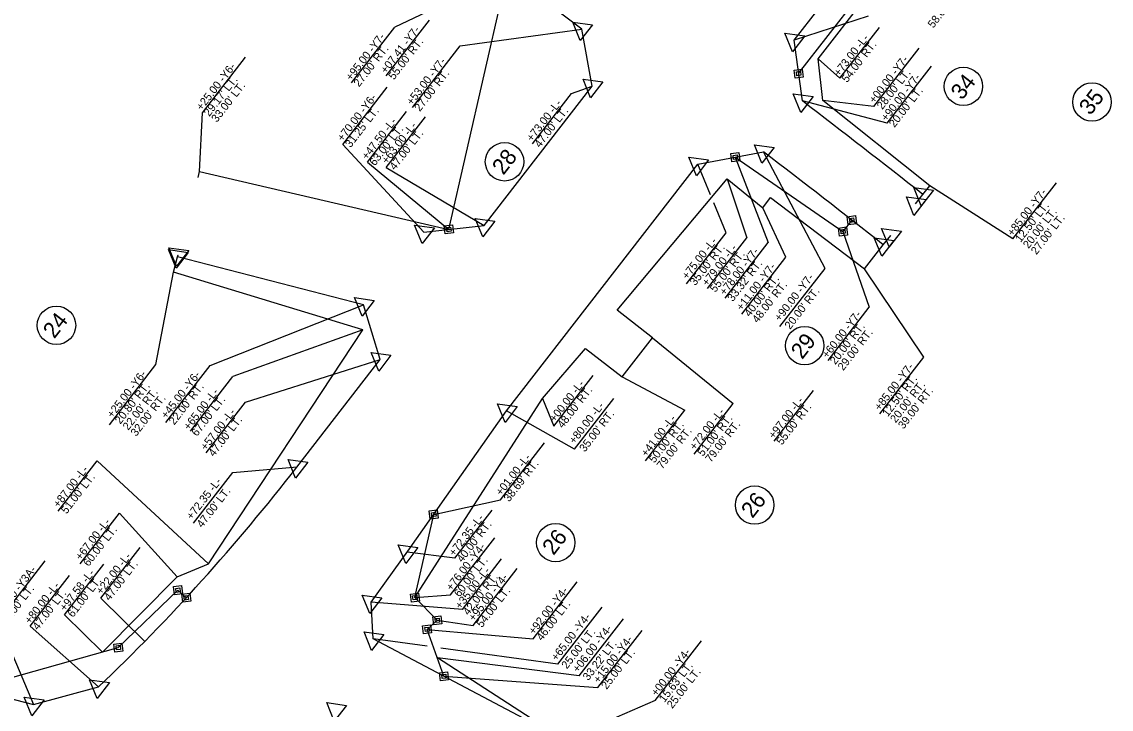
# Model space of a CAD drawing. Extents: x 2010883 to 2014849, y 442000 to 447413.
# Drawn here: x 2014042 to 2014722, y 445299 to 445728 of the extents above; entities that cross this region are included whole.
import ezdxf

# ---------------------------------------------------------------- set-up
doc = ezdxf.new("R2010")
doc.units = 0
for name, color, linetype in [('Prop Easement Construction', 7, 'Continuous'), ('Prop Easement Construction Station Offsets', 7, 'Continuous'), ('Prop Easement Permanent Drainage Utility', 7, 'Continuous'), ('Prop Easement Permanent Drainage Utility Station Offsets', 7, 'Continuous'), ('Prop Easement Permanent Utility', 7, 'Continuous'), ('Prop Easement Permanent Utility Station Offsets', 7, 'Continuous'), ('Prop Parcel Number CELL', 7, 'Continuous'), ('Prop Parcel Number Text', 7, 'Continuous'), ('Prop ROW Marker CELL', 7, 'Continuous'), ('Prop ROW Permanent Easement CELL', 7, 'Continuous'), ('Prop ROW RW Lines', 7, 'Continuous'), ('Prop ROW Station Offsets', 7, 'Continuous')]:
    doc.layers.add(name, color=color, linetype=linetype)

msp = doc.modelspace()

# ---------------------------------------------------------------- linework, layer by layer
at = {"layer": 'Prop Easement Construction'}
for p, q in [((2014539.38, 445704.73), (2014617.83, 445805.87)), ((2014542.4, 445678.69), (2014539.38, 445704.73)), ((2014609.15, 445625.51), (2014542.4, 445678.69)), ((2014152.11, 445630.72), (2014153.06, 445634.43)), ((2014153.06, 445634.43), (2014308.73, 445598.23)), ((2014413.83, 445547.73), (2014482.57, 445629.84)), ((2014482.57, 445629.84), (2014504.77, 445611.75)), ((2014604.82, 445620.01), (2014609.15, 445625.51)), ((2014504.77, 445611.75), (2014509.66, 445618.09)), ((2014509.66, 445618.09), (2014568.31, 445573.66)), ((2014568.31, 445573.66), (2014580.07, 445588.59)), ((2014136.82, 445571.49), (2014139.32, 445581.17)), ((2014255.01, 445535.5), (2014136.82, 445571.49)), ((2014435.96, 445530.58), (2014413.83, 445547.73)), ((2014158.53, 445389.38), (2014255.01, 445535.5)), ((2014416.96, 445506.08), (2014435.96, 445530.58)), ((2014367.34, 445492.68), (2014394.04, 445523.85)), ((2014394.04, 445523.85), (2014416.96, 445506.08)), ((2014287.55, 445368.24), (2014367.34, 445492.68)), ((2014139.04, 445381.17), (2014158.53, 445389.38)), ((2014092.37, 445334.23), (2014139.04, 445381.17)), ((2014380.88, 445279.41), (2014301.58, 445330.55))]:
    msp.add_line(p, q, dxfattribs=at)
at = {"layer": 'Prop Easement Construction Station Offsets'}
for p, q in [((2014269.69, 445694.09), (2014296.66, 445728.85)), ((2014553.01, 445692.61), (2014577.65, 445724.38)), ((2014574.22, 445675.03), (2014602.41, 445711.38)), ((2014154.86, 445671.14), (2014181.82, 445705.91)), ((2014553.01, 445692.61), (2014539.38, 445704.73)), ((2014574.22, 445675.03), (2014542.4, 445678.69)), ((2014153.06, 445634.43), (2014154.86, 445671.14)), ((2014482.57, 445629.84), (2014494.8, 445593.01)), ((2014519.22, 445580.94), (2014504.77, 445611.75)), ((2014470.29, 445561.4), (2014494.8, 445593.01)), ((2014491.64, 445545.38), (2014519.22, 445580.94)), ((2014255.01, 445535.5), (2014173.91, 445506.4)), ((2014435.96, 445530.58), (2014486.38, 445489.46)), ((2014147.4, 445472.22), (2014173.91, 445506.4)), ((2014374.34, 445475.39), (2014398.85, 445507)), ((2014416.96, 445506.08), (2014456.06, 445485.3)), ((2014367.34, 445492.68), (2014374.34, 445475.39)), ((2014431.55, 445453.69), (2014456.06, 445485.3)), ((2014461.87, 445457.85), (2014486.38, 445489.46)), ((2014064.63, 445422.14), (2014089.14, 445453.75)), ((2014158.53, 445389.38), (2014089.14, 445453.75)), ((2014078.46, 445389.31), (2014102.97, 445420.92)), ((2014139.04, 445381.17), (2014102.97, 445420.92)), ((2014068.66, 445357.45), (2014093.17, 445389.06)), ((2014092.37, 445334.23), (2014068.66, 445357.45))]:
    msp.add_line(p, q, dxfattribs=at)
at = {"layer": 'Prop Easement Permanent Drainage Utility'}
msp.add_line((2014308.73, 445598.23), (2014345.35, 445758.1), dxfattribs=at)
at = {"layer": 'Prop Easement Permanent Drainage Utility Station Offsets'}
for p, q in [((2014345.35, 445758.1), (2014274.92, 445724.48)), ((2014247.95, 445689.71), (2014274.92, 445724.48)), ((2014257.87, 445640.26), (2014282.39, 445671.87)), ((2014257.87, 445640.26), (2014308.73, 445598.23))]:
    msp.add_line(p, q, dxfattribs=at)
at = {"layer": 'Prop Easement Permanent Utility'}
for p, q in [((2014527.22, 445695.57), (2014614.67, 445808.33)), ((2014555.48, 445658.51), (2014555.48, 445658.51)), ((2014487.67, 445643.35), (2014554.91, 445596.89)), ((2014560.46, 445603.98), (2014554.91, 445596.89)), ((2014287.55, 445368.24), (2014299.31, 445420.15)), ((2014102.28, 445337), (2014139.57, 445372.88)), ((2014144.72, 445368.14), (2014139.57, 445372.88)), ((2014301.55, 445354.06), (2014287.55, 445368.24)), ((2014295.17, 445348.39), (2014301.55, 445354.06)), ((2014305.71, 445319.08), (2014295.17, 445348.39)), ((2014020.47, 445314.08), (2014102.28, 445337))]:
    msp.add_line(p, q, dxfattribs=at)
at = {"layer": 'Prop Easement Permanent Utility Station Offsets'}
for p, q in [((2014487.67, 445643.35), (2014508.28, 445589.95)), ((2014554.91, 445596.89), (2014571.27, 445549.56)), ((2014481.31, 445555.18), (2014508.28, 445589.95)), ((2014545.57, 445516.43), (2014571.27, 445549.56)), ((2014512, 445465.91), (2014536.51, 445497.52)), ((2014340.94, 445429.35), (2014368.51, 445464.91)), ((2014299.31, 445420.15), (2014340.94, 445429.35)), ((2014309.87, 445369.91), (2014337.45, 445405.47)), ((2014091.44, 445367.84), (2014115.95, 445399.45)), ((2014323.91, 445350.84), (2014351.48, 445386.4)), ((2014361.4, 445342.54), (2014388.98, 445378.1)), ((2014287.55, 445368.24), (2014309.87, 445369.91)), ((2014118.81, 445340.9), (2014091.44, 445367.84)), ((2014295.17, 445348.39), (2014361.4, 445342.54)), ((2014301.55, 445354.06), (2014323.91, 445350.84)), ((2014401.83, 445312.18), (2014429.41, 445347.74)), ((2014305.71, 445319.08), (2014401.83, 445312.18))]:
    msp.add_line(p, q, dxfattribs=at)
at = {"layer": 'Prop Parcel Number CELL'}
for p, q in [((2014630.14, 445687.57), (2014630.14, 445687.57)), ((2014710.45, 445677.79), (2014710.45, 445677.79)), ((2014343.53, 445640.46), (2014343.53, 445640.46)), ((2014063.67, 445538.3), (2014063.67, 445538.3)), ((2014531.02, 445525.59), (2014531.02, 445525.59)), ((2014499.75, 445426.02), (2014499.75, 445426.02)), ((2014375.49, 445402.58), (2014375.49, 445402.58))]:
    msp.add_line(p, q, dxfattribs=at)
for centre in [(2014630.14, 445687.57), (2014710.45, 445677.79), (2014343.53, 445640.46), (2014063.67, 445538.3), (2014531.02, 445525.59), (2014499.75, 445426.02), (2014375.49, 445402.58)]:
    msp.add_circle(centre, 12, dxfattribs=at)
at = {"layer": 'Prop ROW Marker CELL'}
for p, q in [((2014391.79, 445723.35), (2014391.79, 445723.35)), ((2014524.37, 445716.37), (2014524.37, 445716.37)), ((2014527.22, 445695.57), (2014527.22, 445695.57)), ((2014398.29, 445687.6), (2014398.29, 445687.6)), ((2014529.57, 445678.45), (2014529.57, 445678.45)), ((2014487.67, 445643.35), (2014487.67, 445643.35)), ((2014505.25, 445646.68), (2014505.25, 445646.68)), ((2014464.31, 445638.93), (2014464.31, 445638.93)), ((2014600.18, 445614.12), (2014600.18, 445614.12)), ((2014604.82, 445620.01), (2014604.82, 445620.01)), ((2014330.88, 445600.68), (2014330.88, 445600.68)), ((2014560.46, 445603.98), (2014560.46, 445603.98)), ((2014293.03, 445596.5), (2014293.03, 445596.5)), ((2014308.73, 445598.23), (2014308.73, 445598.23)), ((2014554.91, 445596.89), (2014554.91, 445596.89)), ((2014584.71, 445594.48), (2014584.71, 445594.48)), ((2014580.07, 445588.59), (2014580.07, 445588.59)), ((2014139.32, 445581.17), (2014139.32, 445581.17)), ((2014139.62, 445582.33), (2014139.62, 445582.33)), ((2014255.51, 445551.19), (2014255.51, 445551.19)), ((2014265.92, 445516.92), (2014265.92, 445516.92)), ((2014344.81, 445484.84), (2014344.81, 445484.84)), ((2014214.04, 445450.02), (2014214.04, 445450.02)), ((2014299.31, 445420.15), (2014299.31, 445420.15)), ((2014282.78, 445396.71), (2014282.78, 445396.71)), ((2014139.57, 445372.88), (2014139.57, 445372.88)), ((2014144.72, 445368.14), (2014144.72, 445368.14)), ((2014260.31, 445365.36), (2014260.31, 445365.36)), ((2014287.55, 445368.24), (2014287.55, 445368.24)), ((2014295.17, 445348.39), (2014295.17, 445348.39)), ((2014301.55, 445354.06), (2014301.55, 445354.06)), ((2014261.49, 445342.42), (2014261.49, 445342.42)), ((2014102.28, 445337), (2014102.28, 445337)), ((2014305.71, 445319.08), (2014305.71, 445319.08)), ((2014090.02, 445312.45), (2014090.02, 445312.45)), ((2014049.27, 445301.55), (2014049.27, 445301.55))]:
    msp.add_line(p, q, dxfattribs=at)
for points in [[(2014390.8, 445716.21), (2014386.1, 445727.76), (2014398.46, 445726.09)], [(2014523.38, 445709.23), (2014518.68, 445720.78), (2014531.04, 445719.1)], [(2014397.3, 445680.46), (2014392.6, 445692.02), (2014404.96, 445690.34)], [(2014528.58, 445671.3), (2014523.88, 445682.86), (2014536.24, 445681.18)], [(2014504.27, 445639.54), (2014499.56, 445651.09), (2014511.93, 445649.42)], [(2014463.33, 445631.79), (2014458.62, 445643.34), (2014470.99, 445641.66)], [(2014603.83, 445612.87), (2014599.13, 445624.42), (2014611.49, 445622.74)], [(2014599.19, 445606.97), (2014594.49, 445618.53), (2014606.85, 445616.85)], [(2014292.04, 445589.35), (2014287.34, 445600.91), (2014299.7, 445599.23)], [(2014329.89, 445593.54), (2014325.19, 445605.09), (2014337.55, 445603.41)], [(2014583.72, 445587.34), (2014579.02, 445598.89), (2014591.38, 445597.21)], [(2014138.63, 445575.19), (2014133.93, 445586.74), (2014146.29, 445585.06)], [(2014579.08, 445581.44), (2014574.38, 445593), (2014586.74, 445591.32)], [(2014138.34, 445574.03), (2014133.63, 445585.58), (2014146, 445583.9)], [(2014254.53, 445544.04), (2014249.83, 445555.6), (2014262.19, 445553.92)], [(2014264.93, 445509.77), (2014260.23, 445521.33), (2014272.59, 445519.65)], [(2014343.82, 445477.7), (2014339.12, 445489.25), (2014351.48, 445487.57)], [(2014213.05, 445442.88), (2014208.35, 445454.44), (2014220.71, 445452.76)], [(2014281.8, 445389.56), (2014277.1, 445401.12), (2014289.46, 445399.44)], [(2014259.32, 445358.22), (2014254.62, 445369.77), (2014266.98, 445368.09)], [(2014260.5, 445335.27), (2014255.8, 445346.83), (2014268.16, 445345.15)], [(2014089.03, 445305.3), (2014084.33, 445316.86), (2014096.69, 445315.18)], [(2014048.28, 445294.41), (2014043.58, 445305.96), (2014055.94, 445304.28)], [(2014237.17, 445291.05), (2014232.46, 445302.61), (2014244.83, 445300.93)]]:
    msp.add_lwpolyline(points, close=True, dxfattribs=at)
at = {"layer": 'Prop ROW Permanent Easement CELL'}
for points in [[(2014524.38, 445697.78), (2014529.43, 445698.41), (2014530.06, 445693.36), (2014525.01, 445692.73)], [(2014525.8, 445696.67), (2014528.32, 445696.99), (2014528.64, 445694.47), (2014526.12, 445694.15)], [(2014484.82, 445645.56), (2014489.87, 445646.2), (2014490.51, 445641.15), (2014485.46, 445640.51)], [(2014486.25, 445644.46), (2014488.77, 445644.78), (2014489.09, 445642.25), (2014486.56, 445641.93)], [(2014557.61, 445606.18), (2014562.66, 445606.82), (2014563.3, 445601.77), (2014558.25, 445601.13)], [(2014305.89, 445600.44), (2014310.94, 445601.08), (2014311.58, 445596.03), (2014306.53, 445595.39)], [(2014559.04, 445605.08), (2014561.56, 445605.4), (2014561.88, 445602.87), (2014559.35, 445602.56)], [(2014307.31, 445599.34), (2014309.84, 445599.66), (2014310.15, 445597.13), (2014307.63, 445596.81)], [(2014552.07, 445599.09), (2014557.12, 445599.73), (2014557.76, 445594.68), (2014552.71, 445594.04)], [(2014553.49, 445597.99), (2014556.02, 445598.31), (2014556.34, 445595.78), (2014553.81, 445595.46)], [(2014296.47, 445422.36), (2014301.52, 445423), (2014302.16, 445417.95), (2014297.11, 445417.31)], [(2014297.89, 445421.25), (2014300.41, 445421.57), (2014300.73, 445419.05), (2014298.21, 445418.73)], [(2014136.73, 445375.09), (2014141.78, 445375.73), (2014142.42, 445370.68), (2014137.37, 445370.04)], [(2014138.15, 445373.99), (2014140.68, 445374.31), (2014141, 445371.78), (2014138.47, 445371.46)], [(2014141.87, 445370.34), (2014146.92, 445370.98), (2014147.56, 445365.93), (2014142.51, 445365.29)], [(2014143.3, 445369.24), (2014145.82, 445369.56), (2014146.14, 445367.03), (2014143.62, 445366.71)], [(2014284.71, 445370.44), (2014289.76, 445371.08), (2014290.39, 445366.03), (2014285.34, 445365.39)], [(2014286.13, 445369.34), (2014288.65, 445369.66), (2014288.97, 445367.14), (2014286.45, 445366.82)], [(2014298.71, 445356.27), (2014303.76, 445356.91), (2014304.4, 445351.86), (2014299.35, 445351.22)], [(2014300.13, 445355.17), (2014302.66, 445355.49), (2014302.98, 445352.96), (2014300.45, 445352.64)], [(2014292.32, 445350.6), (2014297.37, 445351.23), (2014298.01, 445346.18), (2014292.96, 445345.54)], [(2014293.74, 445349.49), (2014296.27, 445349.81), (2014296.59, 445347.29), (2014294.06, 445346.97)], [(2014099.44, 445339.21), (2014104.49, 445339.85), (2014105.13, 445334.8), (2014100.08, 445334.16)], [(2014100.86, 445338.11), (2014103.38, 445338.43), (2014103.7, 445335.9), (2014101.18, 445335.58)], [(2014302.86, 445321.29), (2014307.91, 445321.93), (2014308.55, 445316.88), (2014303.5, 445316.24)], [(2014304.28, 445320.19), (2014306.81, 445320.5), (2014307.13, 445317.98), (2014304.6, 445317.66)]]:
    msp.add_lwpolyline(points, close=True, dxfattribs=at)
at = {"layer": 'Prop ROW RW Lines'}
for p, q in [((2014524.37, 445716.37), (2014605.26, 445820.68)), ((2014391.79, 445723.35), (2014312.29, 445782.85)), ((2014398.29, 445687.6), (2014391.79, 445723.35)), ((2014529.57, 445678.45), (2014524.37, 445716.37)), ((2014330.88, 445600.68), (2014398.29, 445687.6)), ((2014464.31, 445638.93), (2014505.25, 445646.68)), ((2014344.81, 445484.84), (2014464.31, 445638.93)), ((2014600.18, 445614.12), (2014604.82, 445620.01)), ((2014293.03, 445596.5), (2014330.88, 445600.68)), ((2014580.07, 445588.59), (2014584.71, 445594.48)), ((2014139.32, 445581.17), (2014139.62, 445582.33)), ((2014255.51, 445551.19), (2014139.32, 445581.17)), ((2014265.92, 445516.92), (2014255.51, 445551.19)), ((2014213.83, 445449.76), (2014265.92, 445516.92)), ((2014283.19, 445397.22), (2014344.81, 445484.84)), ((2014260.31, 445365.36), (2014283.19, 445397.22)), ((2014261.49, 445342.42), (2014260.31, 445365.36)), ((2014380.88, 445279.41), (2014261.49, 445342.42)), ((2013942.7, 445328.8), (2014049.27, 445301.55)), ((2014049.27, 445301.55), (2014090.02, 445312.45))]:
    msp.add_line(p, q, dxfattribs=at)
for centre, radius, start, end in [((2010378.3, 440254.75), 6830.04, 51.770498, 52.569773), ((2010378.3, 440254.75), 6790.04, 51.770498, 52.569773), ((2013223.9, 446217.91), 1253, 313.72775, 322.18989)]:
    msp.add_arc(centre, radius, start, end, dxfattribs=at)
at = {"layer": 'Prop ROW Station Offsets'}
for p, q in [((2014570.56, 445731.5), (2014524.37, 445716.37)), ((2014315.9, 445712.89), (2014391.79, 445723.35)), ((2014286.07, 445674.43), (2014315.9, 445712.89)), ((2014582.6, 445664.55), (2014610.21, 445700.15)), ((2014242.5, 445651.24), (2014270.21, 445686.97)), ((2014360.91, 445651.61), (2014385.42, 445683.22)), ((2014385.42, 445683.22), (2014398.29, 445687.6)), ((2014582.6, 445664.55), (2014529.57, 445678.45)), ((2014269.66, 445636.94), (2014294.24, 445668.64)), ((2014242.5, 445651.24), (2014293.03, 445596.5)), ((2014543.7, 445573.89), (2014505.25, 445646.68)), ((2014269.66, 445636.94), (2014330.88, 445600.68)), ((2014472.15, 445619.92), (2014464.31, 445638.93)), ((2014661.05, 445592.3), (2014688.27, 445627.4)), ((2014661.05, 445592.3), (2014609.15, 445625.51)), ((2014481.95, 445596.13), (2014474.25, 445614.81)), ((2014457.16, 445564.17), (2014481.95, 445596.13)), ((2014515.51, 445537.54), (2014543.7, 445573.89)), ((2014605.44, 445518.51), (2014568.31, 445573.66)), ((2014125.82, 445513.74), (2014136.82, 445571.49)), ((2014159.62, 445513.27), (2014255.51, 445551.19)), ((2014577.86, 445482.95), (2014605.44, 445518.51)), ((2014096.7, 445476.19), (2014125.82, 445513.74)), ((2014132.04, 445477.71), (2014159.62, 445513.27)), ((2014181.66, 445490.36), (2014265.92, 445516.92)), ((2014387.28, 445460.89), (2014411.79, 445492.5)), ((2014157.15, 445458.76), (2014181.66, 445490.36)), ((2014387.28, 445460.89), (2014344.81, 445484.84)), ((2014149.24, 445414.76), (2014173.75, 445446.37)), ((2014173.75, 445446.37), (2014214.04, 445450.02)), ((2014312.55, 445392.77), (2014335.84, 445422.81)), ((2014312.55, 445392.77), (2014282.78, 445396.71)), ((2014027.25, 445353.3), (2014056.66, 445391.23)), ((2014317.22, 445360.84), (2014341.73, 445392.45)), ((2014047.28, 445350.38), (2014071.79, 445381.99)), ((2014317.22, 445360.84), (2014260.31, 445365.36)), ((2014376.84, 445326.66), (2014404.42, 445362.22)), ((2014390.19, 445319.38), (2014417.77, 445354.94)), ((2014027.25, 445353.3), (2014049.27, 445301.55)), ((2014047.28, 445350.38), (2014090.02, 445312.45)), ((2014295.24, 445337.81), (2014261.49, 445342.42)), ((2014376.84, 445326.66), (2014303.69, 445336.65)), ((2014437.69, 445304.01), (2014466.49, 445341.15)), ((2014390.19, 445319.38), (2014301.58, 445330.55)), ((2014437.69, 445304.01), (2014380.88, 445279.41))]:
    msp.add_line(p, q, dxfattribs=at)

# ---------------------------------------------------------------- texts
at = {"layer": 'Prop Easement Construction Station Offsets'}
for s, p in [("58.00' RT.", (2014611.31, 445723.6)), ('+07.41 -Y7-', (2014269.49, 445695.1)), ("55.00' RT.", (2014274.43, 445691.27)), ('+73.00 -L-', (2014552.54, 445693.39)), ("54.00' RT.", (2014557.47, 445689.56)), ('+00.00 -Y7-', (2014574.55, 445676.56)), ('+25.00 -Y6-', (2014154.38, 445672.07)), ("28.00' LT.", (2014579.49, 445672.73)), ("29.17' LT.", (2014159.12, 445668.4)), ("33.00' LT.", (2014163.86, 445664.72)), ('+79.00 -L-', (2014470.25, 445562.35)), ("55.00' RT.", (2014475.19, 445558.52)), ('+11.00 -Y7-', (2014491.72, 445547.06)), ("40.00' RT.", (2014496.66, 445543.23)), ("48.00' RT.", (2014501.6, 445539.4)), ('+00.00 -L-', (2014374.98, 445477.47)), ("48.00' RT.", (2014379.92, 445473.64)), ('+65.00 -L-', (2014146.49, 445472.41)), ("67.00' LT.", (2014151.42, 445468.58)), ('+72.00 -L-', (2014462.51, 445459.92)), ('+41.00 -L-', (2014432.18, 445455.77)), ("50.00' RT.", (2014437.12, 445451.94)), ("51.00' RT.", (2014467.44, 445456.09)), ("79.00' RT.", (2014472.38, 445452.26)), ("79.00' RT.", (2014442.06, 445448.11)), ('+87.00 -L-', (2014065.03, 445423.99)), ("51.00' LT.", (2014069.97, 445420.16)), ('+67.00 -L-', (2014078.85, 445391.16)), ("60.00' LT.", (2014083.79, 445387.33)), ('+97.58 -L-', (2014069.06, 445359.3)), ("61.00' LT.", (2014074, 445355.47))]:
    msp.add_text(s, height=5, rotation=52.2051, dxfattribs=at).set_placement(p)
at = {"layer": 'Prop Easement Permanent Drainage Utility Station Offsets'}
for s, p in [('+95.00 -Y7-', (2014247.75, 445690.72)), ("27.00' RT.", (2014252.69, 445686.89)), ('+47.50 -L-', (2014257.64, 445641.36)), ("63.00' LT.", (2014262.58, 445637.53))]:
    msp.add_text(s, height=5, rotation=52.2051, dxfattribs=at).set_placement(p)
at = {"layer": 'Prop Easement Permanent Utility Station Offsets'}
for s, p in [('+78.00 -Y7-', (2014481.17, 445556.58)), ("33.32' RT.", (2014486.11, 445552.75)), ('+60.00 -Y7-', (2014545.23, 445517.28)), ("20.00' RT.", (2014550.17, 445513.45)), ("29.00' RT.", (2014555.1, 445509.62)), ('+97.00 -L-', (2014511.81, 445466.97)), ("55.00' RT.", (2014516.75, 445463.14)), ('+01.00 -L-', (2014341.48, 445431.5)), ("38.69' RT.", (2014346.42, 445427.67)), ('+76.00 -Y4-', (2014310.42, 445372.06)), ('+22.00 -L-', (2014091.84, 445369.69)), ("47.00' LT.", (2014096.78, 445365.86)), ("60.00' LT.", (2014315.35, 445368.23)), ('+95.00 -Y4-', (2014324.45, 445352.99)), ("54.00' LT.", (2014329.39, 445349.16)), ('+92.00 -Y4-', (2014361.95, 445344.69)), ("46.00' LT.", (2014366.88, 445340.86)), ('+15.00 -Y4-', (2014402.38, 445314.33)), ("25.00' LT.", (2014407.32, 445310.5))]:
    msp.add_text(s, height=5, rotation=52.2051, dxfattribs=at).set_placement(p)
at = {"layer": 'Prop Parcel Number Text'}
for s, p in [('34', (2014629.3, 445678.54)), ('35', (2014709.41, 445668.99)), ('28', (2014342.8, 445631.69)), ('24', (2014062.31, 445529.5)), ('29', (2014529.43, 445516.58)), ('26', (2014498.36, 445417.27)), ('26', (2014374.11, 445394.17))]:
    msp.add_text(s, height=10, rotation=52.2051, dxfattribs=at).set_placement(p)
at = {"layer": 'Prop ROW Station Offsets'}
for s, p in [('+53.00 -Y7-', (2014285.69, 445675.35)), ("27.00' RT.", (2014290.63, 445671.52)), ('+90.00 -Y7-', (2014582.14, 445665.34)), ('+70.00 -Y6-', (2014242.42, 445652.77)), ("20.00' LT.", (2014587.08, 445661.51)), ('+73.00 -L-', (2014360.68, 445652.71)), ("31.25' LT.", (2014247.36, 445648.94)), ("47.00' LT.", (2014365.62, 445648.88)), ('+63.00 -L-', (2014270.16, 445638.7)), ("47.00' LT.", (2014275.1, 445634.87)), ('+85.00 -Y7-', (2014660.92, 445593.55)), ("12.50' LT.", (2014665.86, 445589.72)), ("20.00' LT.", (2014670.8, 445585.89)), ("27.00' LT.", (2014675.74, 445582.06)), ('+75.00 -L-', (2014457.75, 445566.56)), ("35.00' RT.", (2014462.68, 445562.73)), ('+90.00 -Y7-', (2014515.48, 445540.4)), ("20.00' RT.", (2014521.9, 445535.42)), ('+85.00 -Y7-', (2014577.94, 445484.63)), ('+25.00 -Y6-', (2014098.64, 445480.05)), ('+45.00 -Y6-', (2014132.34, 445479.55)), ("12.50' RT.", (2014582.88, 445480.8)), ("20.80' RT.", (2014103.58, 445476.22)), ("22.00' RT.", (2014108.52, 445472.39)), ("22.00' RT.", (2014137.28, 445475.72)), ("20.00' RT.", (2014587.82, 445476.97)), ("39.00' RT.", (2014592.76, 445473.14)), ("32.00' RT.", (2014113.46, 445468.56)), ('+57.00 -L-', (2014157.04, 445459.75)), ('+80.00 -L-', (2014387.25, 445463.76)), ("35.00' RT.", (2014393.67, 445458.78)), ("47.00' LT.", (2014161.98, 445455.92)), ('+72.35 -L-', (2014148.24, 445416.46)), ("47.00' LT.", (2014154.66, 445411.48)), ('+72.35 -L-', (2014312.13, 445393.63)), ("40.00' RT.", (2014317.07, 445389.8)), ('+10.00 -Y3A-', (2014027.09, 445354.34)), ('+35.00 -L-', (2014316.06, 445360.61)), ("42.00' RT.", (2014320.99, 445356.78)), ('+80.00 -L-', (2014047.18, 445351.38)), ("25.00' LT.", (2014032.03, 445350.51)), ("47.00' LT.", (2014052.12, 445347.55)), ('+65.00 -Y4-', (2014376.09, 445328.29)), ("25.00' LT.", (2014382.51, 445323.31)), ('+06.00 -Y4-', (2014389.43, 445321)), ("33.22' LT.", (2014395.85, 445316.02)), ('+00.00 -Y4-', (2014438.47, 445306.24)), ("15.63' LT.", (2014443.41, 445302.41)), ("25.00' LT.", (2014448.35, 445298.58))]:
    msp.add_text(s, height=5, rotation=52.2051, dxfattribs=at).set_placement(p)

doc.saveas('drawing.dxf')
